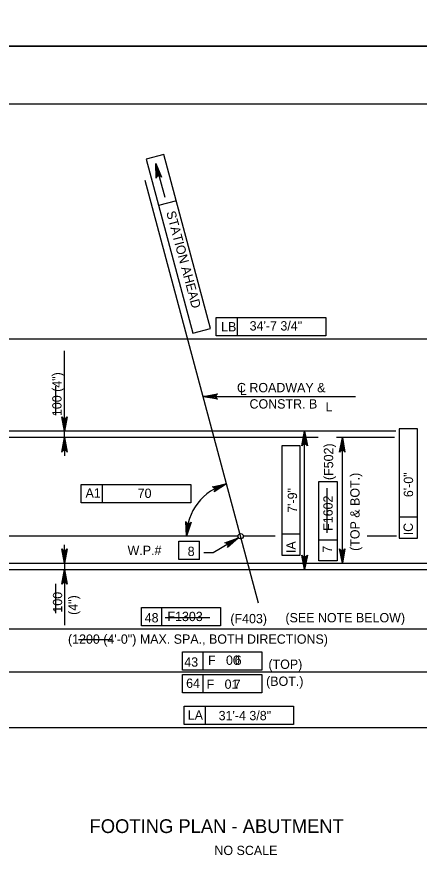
# Model space of a CAD drawing. Extents: x 179 to 454, y -271 to 54.
# Drawn here: x 253.13 to 258.31, y -54.56 to -43.62 of the extents above; entities that cross this region are included whole.
import ezdxf

# ---------------------------------------------------------------- set-up
doc = ezdxf.new("R2010")
doc.units = 0
for name, color, linetype in [('Level 1', 7, 'Continuous'), ('Level 10', 7, 'Continuous'), ('Level 11', 7, 'Continuous'), ('Level 3', 7, 'Continuous'), ('Level 4', 7, 'Continuous'), ('Level 41', 7, 'Continuous'), ('Level 6', 7, 'Continuous'), ('Level 63', 7, 'Continuous')]:
    doc.layers.add(name, color=color, linetype=linetype)

msp = doc.modelspace()

# ---------------------------------------------------------------- linework, layer by layer
at = {"layer": 'Level 1'}
msp.add_lwpolyline([(245.497, -65.25), (276.997, -65.25), (276.997, -44.75), (245.497, -44.75)], close=True, dxfattribs=at)
at = {"layer": 'Level 10'}
for p, q in [((258.015, -48.966), (252.571, -48.966)), ((255.979, -50.319), (251.381, -50.319)), ((256.456, -50.319), (256.047, -50.319)), ((258.024, -50.319), (257.644, -50.319)), ((251.601, -50.75), (260.387, -50.75))]:
    msp.add_line(p, q, dxfattribs=at)
at = {"layer": 'Level 11'}
msp.add_line((256.244, -51.181), (254.784, -45.734), dxfattribs=at)
at = {"layer": 'Level 3'}
for points in [[(253.742, -48.966), (253.707, -48.78), (253.717, -48.794), (253.73, -48.801), (253.742, -48.803), (253.755, -48.801), (253.767, -48.794), (253.777, -48.78), (253.742, -48.966), (253.767, -48.794), (253.755, -48.801), (253.742, -48.966), (253.742, -48.803), (253.73, -48.801), (253.742, -48.966), (253.717, -48.794)], [(253.742, -49.048), (253.777, -49.234), (253.767, -49.22), (253.755, -49.213), (253.742, -49.211), (253.73, -49.213), (253.717, -49.22), (253.707, -49.234), (253.742, -49.048), (253.717, -49.22), (253.73, -49.213), (253.742, -49.048), (253.742, -49.211), (253.755, -49.213), (253.742, -49.048), (253.767, -49.22)]]:
    msp.add_lwpolyline(points, dxfattribs=at)
at = {"layer": 'Level 4'}
for p, q in [((255.024, -45.396), (254.796, -45.457)), ((254.796, -45.457), (255.398, -47.703)), ((255.626, -47.641), (255.024, -45.396)), ((255.039, -45.952), (254.921, -45.514)), ((254.96, -46.051), (255.189, -45.99)), ((255.698, -47.498), (257.11, -47.498)), ((255.698, -47.734), (255.698, -47.498)), ((255.971, -47.734), (255.971, -47.498)), ((257.11, -47.498), (257.11, -47.734)), ((255.398, -47.703), (255.626, -47.641)), ((252.571, -47.775), (259.54, -47.775)), ((257.11, -47.734), (255.698, -47.734)), ((253.742, -48.966), (253.742, -47.928)), ((255.53, -48.517), (255.917, -48.517)), ((255.917, -48.517), (257.492, -48.517)), ((253.742, -48.848), (253.742, -48.73)), ((253.742, -49.048), (253.742, -48.966)), ((256.838, -50.75), (256.838, -48.966)), ((258.056, -48.933), (258.056, -50.345)), ((258.292, -48.933), (258.056, -48.933)), ((258.292, -50.345), (258.292, -48.933)), ((253.742, -49.048), (253.742, -49.284)), ((257.324, -50.668), (257.324, -49.048)), ((256.545, -49.152), (256.545, -50.564)), ((256.781, -49.152), (256.545, -49.152)), ((256.781, -50.564), (256.781, -49.152)), ((257.022, -50.635), (257.022, -49.613)), ((257.022, -49.613), (257.259, -49.613)), ((257.259, -49.613), (257.259, -50.635)), ((253.958, -49.651), (255.37, -49.651)), ((253.958, -49.887), (253.958, -49.651)), ((254.232, -49.887), (254.232, -49.651)), ((255.37, -49.651), (255.37, -49.887)), ((255.37, -49.887), (253.958, -49.887)), ((258.056, -50.071), (258.292, -50.071)), ((256.545, -50.29), (256.781, -50.29)), ((255.218, -50.382), (255.482, -50.382)), ((255.218, -50.618), (255.218, -50.382)), ((255.482, -50.618), (255.482, -50.382)), ((255.986, -50.34), (255.657, -50.535)), ((257.259, -50.371), (257.022, -50.371)), ((258.056, -50.345), (258.292, -50.345)), ((253.742, -50.668), (253.742, -50.432)), ((255.482, -50.618), (255.218, -50.618)), ((255.657, -50.535), (255.539, -50.535)), ((256.545, -50.564), (256.781, -50.564)), ((253.742, -50.668), (253.742, -50.75)), ((253.769, -50.668), (253.919, -50.668)), ((257.259, -50.635), (257.022, -50.635)), ((253.742, -50.75), (253.742, -51.465)), ((253.769, -50.75), (253.919, -50.75)), ((253.742, -50.868), (253.742, -50.986)), ((254.734, -51.236), (255.755, -51.236)), ((254.734, -51.472), (254.734, -51.236)), ((254.997, -51.472), (254.997, -51.236)), ((255.755, -51.236), (255.755, -51.472)), ((255.755, -51.472), (254.734, -51.472)), ((251.683, -51.513), (260.305, -51.513)), ((255.265, -51.809), (256.287, -51.809)), ((255.265, -52.045), (255.265, -51.809)), ((255.529, -52.045), (255.529, -51.809)), ((256.287, -51.809), (256.287, -52.045)), ((251.683, -52.068), (260.305, -52.068)), ((256.287, -52.045), (255.265, -52.045)), ((255.265, -52.1), (256.287, -52.1)), ((255.265, -52.337), (255.265, -52.1)), ((255.529, -52.337), (255.529, -52.1)), ((256.287, -52.1), (256.287, -52.337)), ((256.287, -52.337), (255.265, -52.337)), ((255.284, -52.744), (255.284, -52.508)), ((255.284, -52.508), (256.696, -52.508)), ((255.558, -52.744), (255.558, -52.508)), ((256.696, -52.508), (256.696, -52.744)), ((251.601, -52.785), (260.387, -52.785)), ((256.696, -52.744), (255.284, -52.744))]:
    msp.add_line(p, q, dxfattribs=at)
for points in [[(254.921, -45.514), (254.994, -45.689), (254.981, -45.677), (254.967, -45.673), (254.954, -45.673), (254.943, -45.678), (254.932, -45.688), (254.925, -45.703), (254.921, -45.514), (254.932, -45.688), (254.943, -45.678), (254.921, -45.514), (254.954, -45.673), (254.967, -45.673), (254.921, -45.514), (254.981, -45.677)], [(255.53, -48.517), (255.716, -48.482), (255.702, -48.492), (255.695, -48.505), (255.692, -48.517), (255.695, -48.53), (255.702, -48.542), (255.716, -48.552), (255.53, -48.517), (255.702, -48.542), (255.695, -48.53), (255.53, -48.517), (255.692, -48.517), (255.695, -48.505), (255.53, -48.517), (255.702, -48.492)], [(256.838, -48.966), (256.873, -49.152), (256.863, -49.138), (256.85, -49.131), (256.838, -49.128), (256.825, -49.131), (256.813, -49.138), (256.803, -49.152), (256.838, -48.966), (256.813, -49.138), (256.825, -49.131), (256.838, -48.966), (256.838, -49.128), (256.85, -49.131), (256.838, -48.966), (256.863, -49.138)], [(257.324, -49.048), (257.358, -49.234), (257.349, -49.22), (257.336, -49.213), (257.324, -49.211), (257.311, -49.213), (257.299, -49.22), (257.289, -49.234), (257.324, -49.048), (257.299, -49.22), (257.311, -49.213), (257.324, -49.048), (257.324, -49.211), (257.336, -49.213), (257.324, -49.048), (257.349, -49.22)], [(255.832, -49.645), (255.673, -49.748), (255.682, -49.733), (255.684, -49.719), (255.682, -49.706), (255.675, -49.696), (255.663, -49.687), (255.646, -49.683), (255.832, -49.645), (255.663, -49.687), (255.675, -49.696), (255.832, -49.645), (255.682, -49.706), (255.684, -49.719), (255.832, -49.645), (255.682, -49.733)], [(255.314, -50.319), (255.305, -50.13), (255.313, -50.145), (255.324, -50.154), (255.336, -50.158), (255.349, -50.158), (255.362, -50.152), (255.374, -50.139), (255.314, -50.319), (255.362, -50.152), (255.349, -50.158), (255.314, -50.319), (255.336, -50.158), (255.324, -50.154), (255.314, -50.319), (255.313, -50.145)], [(255.986, -50.34), (255.844, -50.465), (255.851, -50.45), (255.851, -50.435), (255.846, -50.423), (255.838, -50.414), (255.825, -50.407), (255.808, -50.405), (255.986, -50.34), (255.825, -50.407), (255.838, -50.414), (255.986, -50.34), (255.846, -50.423), (255.851, -50.435), (255.986, -50.34), (255.851, -50.45)], [(253.742, -50.668), (253.707, -50.481), (253.717, -50.496), (253.73, -50.503), (253.742, -50.505), (253.755, -50.503), (253.767, -50.496), (253.777, -50.481), (253.742, -50.668), (253.767, -50.496), (253.755, -50.503), (253.742, -50.668), (253.742, -50.505), (253.73, -50.503), (253.742, -50.668), (253.717, -50.496)], [(257.324, -50.668), (257.289, -50.481), (257.299, -50.496), (257.311, -50.503), (257.324, -50.505), (257.336, -50.503), (257.349, -50.496), (257.358, -50.481), (257.324, -50.668), (257.349, -50.496), (257.336, -50.503), (257.324, -50.668), (257.324, -50.505), (257.311, -50.503), (257.324, -50.668), (257.299, -50.496)], [(256.838, -50.75), (256.803, -50.564), (256.813, -50.578), (256.825, -50.585), (256.838, -50.587), (256.85, -50.585), (256.863, -50.578), (256.873, -50.564), (256.838, -50.75), (256.863, -50.578), (256.85, -50.585), (256.838, -50.75), (256.838, -50.587), (256.825, -50.585), (256.838, -50.75), (256.813, -50.578)], [(253.742, -50.75), (253.777, -50.936), (253.767, -50.922), (253.755, -50.915), (253.742, -50.913), (253.73, -50.915), (253.717, -50.922), (253.707, -50.936), (253.742, -50.75), (253.717, -50.922), (253.73, -50.915), (253.742, -50.75), (253.742, -50.913), (253.755, -50.915), (253.742, -50.75), (253.767, -50.922)]]:
    msp.add_lwpolyline(points, dxfattribs=at)
for points in [[(255.653, -48.497), (255.653, -48.537), (255.535, -48.517)], [(253.722, -48.848), (253.762, -48.848), (253.742, -48.966)], [(256.858, -49.084), (256.818, -49.084), (256.838, -48.966)], [(253.722, -49.166), (253.762, -49.166), (253.742, -49.048)], [(257.343, -49.166), (257.304, -49.166), (257.324, -49.048)], [(253.722, -50.55), (253.762, -50.55), (253.742, -50.668)], [(257.343, -50.55), (257.304, -50.55), (257.324, -50.668)], [(256.858, -50.632), (256.818, -50.632), (256.838, -50.75)], [(253.722, -50.868), (253.762, -50.868), (253.742, -50.75)]]:
    msp.add_lwpolyline(points, close=True, dxfattribs=at)
msp.add_circle((256.013, -50.319), 0.034, dxfattribs=at)
msp.add_arc((256.013, -50.319), 0.698, 104.9998, 179.9968, dxfattribs=at)
at = {"layer": 'Level 41'}
for p, q in [((253.629, -48.759), (253.629, -48.383)), ((257.129, -50.275), (257.129, -49.699)), ((253.629, -51.309), (253.629, -50.933)), ((255.038, -51.368), (255.614, -51.368)), ((253.921, -51.649), (254.355, -51.649))]:
    msp.add_line(p, q, dxfattribs=at)
at = {"layer": 'Level 6'}
for p, q in [((257.014, -49.048), (251.642, -49.048)), ((257.998, -49.048), (257.25, -49.048)), ((251.642, -50.668), (260.346, -50.668))]:
    msp.add_line(p, q, dxfattribs=at)
at = {"layer": 'Level 63'}
for points in [[(243.747, -44), (277.747, -44), (277.747, -22), (243.747, -22)], [(243.747, -66), (277.747, -66), (277.747, -44), (243.747, -44)]]:
    msp.add_lwpolyline(points, close=True, dxfattribs=at)

# ---------------------------------------------------------------- texts
at = {"layer": 'Level 4'}
for s, rotation, p in [('STATION AHEAD', 285, (255.053, -46.143)), ('100 (4")', 90, (253.704, -48.77)), ('(F502)', 90, (257.206, -49.595)), ('(TOP & BOT.)', 90, (257.546, -50.508)), ('F1602', 90, (257.199, -50.25)), ('IC', 90, (258.233, -50.307)), ('IA', 90, (256.722, -50.536)), ('100', 90, (253.712, -51.304)), ('(4")', 90, (253.912, -51.333))]:
    msp.add_text(s, height=0.12, rotation=rotation, dxfattribs=at).set_placement(p)
for s, height, p in [('LB', 0.12, (255.761, -47.679)), ('C ROADWAY &', 0.12, (255.965, -48.463)), ('L', 0.12, (256.003, -48.499)), ('CONSTR. B', 0.12, (256.127, -48.673)), ('L', 0.12, (257.107, -48.711)), ('A1', 0.12, (254.013, -49.821)), ('W.P.#', 0.12, (254.555, -50.561)), ('F1303', 0.12, (255.069, -51.413)), ('(F403)', 0.12, (255.88, -51.441)), ('(SEE NOTE BELOW)', 0.12, (256.59, -51.429)), ('(1200 (4\'-0") MAX. SPA., BOTH DIRECTIONS)', 0.12, (253.787, -51.705)), ('F   00', 0.12, (255.592, -51.977)), ('(TOP)', 0.12, (256.371, -52.029)), ('(BOT.)', 0.12, (256.341, -52.248)), ('F   01', 0.12, (255.574, -52.286)), ('LA', 0.12, (255.331, -52.685)), ('FOOTING PLAN - ABUTMENT', 0.17717, (254.065, -54.145)), ('NO SCALE', 0.12, (255.675, -54.429))]:
    msp.add_text(s, height=height, dxfattribs=at).set_placement(p)
at = {"layer": 'Level 41'}
for s, p in [('34\'-7 3/4"', (256.129, -47.667)), ('70', (254.685, -49.825)), ('8', (255.33, -50.574)), ('48', (254.776, -51.43)), ('43', (255.286, -52.001)), ('6', (255.936, -51.977)), ('64', (255.31, -52.274)), ('7', (255.924, -52.286)), ('31\'-4 3/8"', (255.729, -52.691))]:
    msp.add_text(s, height=0.12, dxfattribs=at).set_placement(p)
for s, p in [('6\'-0"', (258.236, -49.815)), ('7\'-9"', (256.74, -50.017)), ('7', (257.19, -50.532))]:
    msp.add_text(s, height=0.12, rotation=90, dxfattribs=at).set_placement(p)

doc.saveas('drawing.dxf')
